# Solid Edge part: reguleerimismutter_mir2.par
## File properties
Author: KULL
Template: Iso Metric Part.par
Last saved by: KULL
Revision: 2
Application: Solid Edge
Accuracy: 0,990
Username: KULL
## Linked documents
reguleerimismutter.par
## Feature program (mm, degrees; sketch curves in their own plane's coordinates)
part copy "CopiedPart_1"
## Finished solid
Body 1: solid body, 53 faces, 109 edges, 58 vertices.
  Faces by surface: cylinder 25, plane 13, torus 13, spline 2
  Edges by curve: circle 63, line 36, spline 6, intersection 4
Bounding box of the edges (mm; curved faces can reach further): 7.400 x 6.924 x 7.706, from (-346.16, -88.924, 49.5908) to (-338.76, -82.0002, 57.297).
Cylindrical faces by radius (mm): R0.1 x12, R0.3 x6, R1.2428 x1, R2 x2, R2.5057 x1, R3 x2, R3.7 x1
Toroidal faces (ring radius, tube radius in mm): R0.2 r0.1 x6, R0.4 r0.1 x6, R3.6 r0.1 x1
Planar faces by outward normal: oblique 13
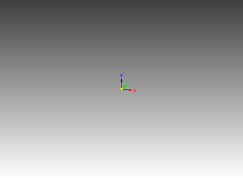
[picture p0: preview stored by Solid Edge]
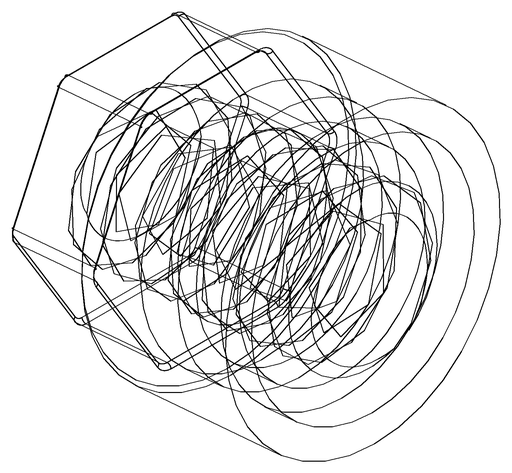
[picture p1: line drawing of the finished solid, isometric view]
